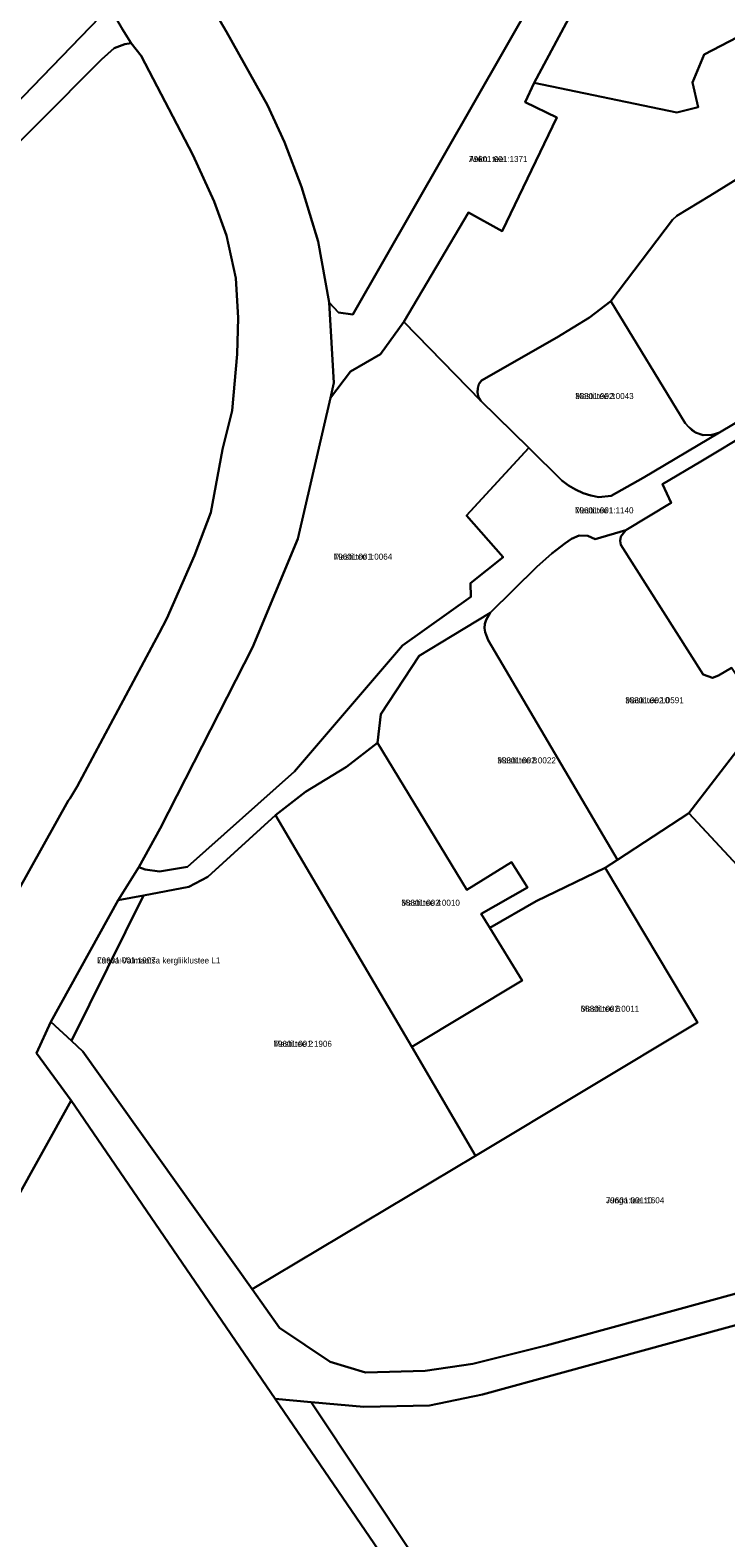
# Model space of a CAD drawing. Extents: x 625111 to 706696, y 6474150 to 6504223.
# Drawn here: x 638778 to 638950.5, y 6485129 to 6485502.8 of the extents above; entities that cross this region are included whole.
import ezdxf

# ---------------------------------------------------------------- set-up
doc = ezdxf.new("R2010")
doc.units = 0
for name, color, linetype in [('L_AADRESS', 7, 'Continuous'), ('PIIR', 7, 'Continuous'), ('TUNNUS', 7, 'Continuous')]:
    doc.layers.add(name, color=color, linetype=linetype)

msp = doc.modelspace()

# ---------------------------------------------------------------- linework, layer by layer
at = {"layer": 'PIIR'}
for points in [[(638782.67, 6485576.05), (638784.4, 6485579.3), (638790.71, 6485583.98), (638802.36, 6485586.41), (638817.08, 6485589.14), (638874.86, 6485597.99), (638894.65, 6485601.55), (638898.79, 6485597.02), (638907.54, 6485567.11), (638909.56, 6485556.39), (638909.87, 6485545.2), (638908.04, 6485527.28), (638906.6, 6485519.92), (638903.1, 6485511.25), (638858.04, 6485432.29), (638854.47, 6485432.84), (638852.13, 6485435.31), (638849.42, 6485450.41), (638845.25, 6485463.97), (638841.03, 6485475.01), (638836.81, 6485484.18), (638826.7, 6485502.4), (638802.18, 6485544.13)], [(638742.82, 6485568.79), (638781.99, 6485513.33), (638795.27, 6485512.53), (638796.61, 6485512.41), (638798.39, 6485509.3), (638797.64, 6485508.52), (638759.55, 6485469.21), (638758.48, 6485470.2), (638720.26, 6485531.5)], [(638616.72, 6485315.58), (638570.26, 6485268.85), (638564.72, 6485271.94), (638633.01, 6485342.2), (638632.31, 6485342.92), (638717.29, 6485427.39), (638718, 6485426.69), (638736.44, 6485445.14), (638750.53, 6485459.52), (638759.55, 6485469.21), (638797.64, 6485508.52), (638800.82, 6485503.13), (638803.01, 6485499.59), (638801.49, 6485499.35), (638798.84, 6485498.32), (638795.69, 6485495.51), (638747.94, 6485447.72), (638716.99, 6485416.28), (638708.55, 6485409.73)], [(638982.43, 6485427.28), (638978.84, 6485424.81), (638971.8, 6485420.65), (638963.59, 6485415.55), (638965.5, 6485412.9), (638948.95, 6485403.05), (638947.96, 6485402.69), (638946.97, 6485402.47), (638945.96, 6485402.38), (638944.88, 6485402.38), (638943.92, 6485402.7), (638942.97, 6485403.08), (638942.09, 6485403.64), (638941.29, 6485404.34), (638940.45, 6485405.39), (638921.96, 6485435.63), (638937.31, 6485455.82), (638938.31, 6485456.75), (638946.5, 6485461.77), (638953.47, 6485466.04), (638956.67, 6485467.85)], [(638948.95, 6485403.05), (638930.04, 6485391.8), (638922.06, 6485387.38), (638919.02, 6485387.06), (638916.99, 6485387.41), (638915.09, 6485388.01), (638913.21, 6485388.89), (638911.46, 6485389.89), (638909.87, 6485391.12), (638901.61, 6485399.25), (638889.74, 6485410.92), (638889.17, 6485411.85), (638888.93, 6485412.95), (638889, 6485414.06), (638889.27, 6485415.02), (638889.91, 6485415.96), (638908.61, 6485426.63), (638916.66, 6485431.54), (638921.96, 6485435.63), (638940.45, 6485405.39), (638941.29, 6485404.34), (638942.97, 6485403.08), (638944.88, 6485402.38), (638946.97, 6485402.47), (638947.96, 6485402.69)], [(638887.17, 6485365.73), (638887.26, 6485362.34), (638870.32, 6485350.21), (638843.57, 6485319.03), (638817.01, 6485295.37), (638810.1, 6485294.23), (638806.47, 6485294.72), (638804.94, 6485295.29), (638810.23, 6485304.88), (638833.13, 6485349.78), (638844.35, 6485376.71), (638852.48, 6485411.67), (638857.46, 6485418.19), (638864.83, 6485422.47), (638870.65, 6485430.46), (638889.74, 6485410.92), (638901.61, 6485399.25), (638886.18, 6485382.44), (638895.32, 6485372.15)], [(638925.68, 6485378.85), (638936.93, 6485385.6), (638934.77, 6485390.22), (638944.32, 6485395.86), (638956.91, 6485403.45), (638971.58, 6485412.28), (638989.73, 6485393.14), (638994.84, 6485389.32), (638990.6, 6485376.31), (638978.8, 6485363.93), (638966.42, 6485342.25), (638956.01, 6485341.65), (638955.05, 6485341.15), (638954.02, 6485341.48), (638951.88, 6485344.74), (638948.66, 6485342.79), (638947.17, 6485342.22), (638944.9, 6485343.05), (638924.49, 6485375.18), (638924.28, 6485376.2), (638924.43, 6485377.27)], [(638864.91, 6485333.2), (638874.47, 6485347.71), (638882.64, 6485352.68), (638892.04, 6485358.36), (638891.05, 6485356.61), (638890.75, 6485355.61), (638890.67, 6485354.58), (638890.85, 6485353.53), (638891.59, 6485351.53), (638923.6, 6485297.08), (638920.59, 6485295.11), (638903.44, 6485286.84), (638891.98, 6485280.22), (638889.85, 6485283.75), (638901.29, 6485290.24), (638897.36, 6485296.49), (638886.28, 6485289.68), (638864.1, 6485326.11)], [(638941.32, 6485308.7), (638960.45, 6485333.44), (638988.09, 6485314), (638994.99, 6485304.53), (638996.71, 6485300.14), (638970.95, 6485276.89)], [(638846.23, 6485314), (638856.41, 6485320.13), (638864.1, 6485326.11), (638886.28, 6485289.68), (638897.36, 6485296.49), (638901.29, 6485290.24), (638889.85, 6485283.75), (638891.98, 6485280.22), (638899.97, 6485267.18), (638872.63, 6485250.71), (638838.82, 6485308.17)], [(638788.23, 6485252.22), (638806.08, 6485288.26), (638817.33, 6485290.37), (638822.08, 6485292.86), (638838.82, 6485308.17), (638872.63, 6485250.71), (638888.4, 6485223.75), (638833.02, 6485190.63), (638791.06, 6485249.59)], [(638899.97, 6485267.18), (638891.98, 6485280.22), (638903.44, 6485286.84), (638920.59, 6485295.11), (638943.51, 6485256.8), (638888.4, 6485223.75), (638872.63, 6485250.71)], [(638788.23, 6485252.22), (638783.12, 6485256.93), (638799.77, 6485287.11), (638806.08, 6485288.26)], [(638931.59, 6485002.42), (638870.49, 6484835.17), (638723.26, 6485120.65), (638788.19, 6485237.4), (638838.72, 6485163.5), (638933.57, 6485024.77), (638938.01, 6485026.87), (639015.85, 6485066.04), (639017.1, 6485021.15)], [(638847.7, 6485162.63), (638860.71, 6485161.51), (638876.99, 6485161.83), (638890.17, 6485164.52), (639009.68, 6485197.31), (639015.85, 6485066.04), (638938.01, 6485026.87)], [(638838.72, 6485163.5), (638847.7, 6485162.63), (638938.01, 6485026.87), (638933.57, 6485024.77)]]:
    msp.add_lwpolyline(points, close=True, dxfattribs=at)
for points in [[(638802.18, 6485544.13), (638826.7, 6485502.4), (638836.81, 6485484.18), (638841.03, 6485475.01), (638845.25, 6485463.97), (638849.42, 6485450.41), (638852.13, 6485435.31), (638853.33, 6485415.33), (638852.48, 6485411.67), (638844.35, 6485376.71), (638833.13, 6485349.78), (638810.23, 6485304.88), (638804.94, 6485295.29), (638799.77, 6485287.11), (638783.12, 6485256.93), (638779.54, 6485249.16), (638788.19, 6485237.4), (638723.26, 6485120.65), (638562.67, 6484825.18), (638546.32, 6484825.91)], [(638912.12, 6485506.89), (638903, 6485489.78), (638900.75, 6485484.94), (638908.61, 6485481.14), (638895.06, 6485452.96), (638886.66, 6485457.57), (638870.65, 6485430.46), (638864.83, 6485422.47), (638857.46, 6485418.19), (638852.48, 6485411.67), (638853.33, 6485415.33), (638852.13, 6485435.31), (638854.47, 6485432.84), (638858.04, 6485432.29), (638903.1, 6485511.25)], [(639223.56, 6485267.38), (639212.2, 6485260.95), (639164.58, 6485309.39), (639145.62, 6485330.59), (639134.89, 6485344.87), (639122.99, 6485356.67), (639105.9, 6485372.5), (639098.87, 6485379.9), (639082.01, 6485394.58), (639069.1, 6485403.36), (639040.99, 6485429.13), (639026.45, 6485443.33), (639024.74, 6485447.28), (639021.42, 6485450.35), (638977.35, 6485491.09), (638966.87, 6485497.91), (638953.41, 6485501.05), (638945.14, 6485496.81), (638942.22, 6485489.86), (638943.68, 6485483.71), (638938.35, 6485482.36), (638903, 6485489.78), (638912.12, 6485506.89)], [(638528.72, 6484862.32), (638686.3, 6485153.17), (638689.4, 6485161.09), (638736.24, 6485245.3), (638745.8, 6485237.26), (638787.4, 6485311.71), (638787.91, 6485312.41), (638789.67, 6485315.31), (638809.97, 6485353.32), (638811.86, 6485356.95), (638818.71, 6485372.53), (638822.76, 6485383.22), (638825.69, 6485398.82), (638828.12, 6485408.53), (638829.36, 6485422.49), (638829.6, 6485431.48), (638829.02, 6485441.3), (638826.69, 6485451.91), (638823.64, 6485460.32), (638818.36, 6485471.86), (638805.53, 6485496.41), (638803.01, 6485499.59), (638800.82, 6485503.13)], [(638747.94, 6485447.72), (638795.69, 6485495.51), (638798.84, 6485498.32), (638801.49, 6485499.35), (638803.01, 6485499.59), (638805.53, 6485496.41), (638818.36, 6485471.86), (638823.64, 6485460.32), (638826.69, 6485451.91), (638829.02, 6485441.3), (638829.6, 6485431.48), (638829.36, 6485422.49), (638828.12, 6485408.53), (638825.69, 6485398.82), (638822.76, 6485383.22), (638818.71, 6485372.53), (638811.86, 6485356.95), (638809.97, 6485353.32), (638789.67, 6485315.31), (638787.91, 6485312.41), (638787.4, 6485311.71), (638745.8, 6485237.26)], [(638953.47, 6485466.04), (638946.5, 6485461.77), (638938.31, 6485456.75), (638937.31, 6485455.82), (638921.96, 6485435.63), (638916.66, 6485431.54), (638908.61, 6485426.63), (638889.91, 6485415.96), (638889.27, 6485415.02), (638889, 6485414.06), (638888.93, 6485412.95), (638889.17, 6485411.85), (638889.74, 6485410.92), (638870.65, 6485430.46), (638886.66, 6485457.57), (638895.06, 6485452.96), (638908.61, 6485481.14), (638900.75, 6485484.94), (638903, 6485489.78), (638938.35, 6485482.36), (638943.68, 6485483.71), (638942.22, 6485489.86), (638945.14, 6485496.81), (638953.41, 6485501.05)], [(638956.91, 6485403.45), (638944.32, 6485395.86), (638934.77, 6485390.22), (638936.93, 6485385.6), (638925.68, 6485378.85), (638918.07, 6485376.58), (638916.25, 6485377.47), (638914.16, 6485377.51), (638912.2, 6485376.68), (638910.54, 6485375.55), (638907.37, 6485373.04), (638903.62, 6485369.72), (638892.04, 6485358.36), (638882.64, 6485352.68), (638874.47, 6485347.71), (638864.91, 6485333.2), (638864.1, 6485326.11), (638856.41, 6485320.13), (638846.23, 6485314), (638838.82, 6485308.17), (638822.08, 6485292.86), (638817.33, 6485290.37), (638806.08, 6485288.26), (638799.77, 6485287.11), (638804.94, 6485295.29), (638806.47, 6485294.72), (638810.1, 6485294.23), (638817.01, 6485295.37), (638843.57, 6485319.03), (638870.32, 6485350.21), (638887.26, 6485362.34), (638887.17, 6485365.73), (638895.32, 6485372.15), (638886.18, 6485382.44), (638901.61, 6485399.25), (638909.87, 6485391.12), (638911.46, 6485389.89), (638913.21, 6485388.89), (638915.09, 6485388.01), (638916.99, 6485387.41), (638919.02, 6485387.06), (638922.06, 6485387.38), (638930.04, 6485391.8), (638948.95, 6485403.05), (638965.5, 6485412.9)], [(638960.45, 6485333.44), (638941.32, 6485308.7), (638923.6, 6485297.08), (638891.59, 6485351.53), (638890.85, 6485353.53), (638890.67, 6485354.58), (638890.75, 6485355.61), (638891.05, 6485356.61), (638892.04, 6485358.36), (638903.62, 6485369.72), (638907.37, 6485373.04), (638910.54, 6485375.55), (638912.2, 6485376.68), (638914.16, 6485377.51), (638916.25, 6485377.47), (638918.07, 6485376.58), (638925.68, 6485378.85), (638924.43, 6485377.27), (638924.28, 6485376.2), (638924.49, 6485375.18), (638944.9, 6485343.05), (638947.17, 6485342.22), (638948.66, 6485342.79), (638951.88, 6485344.74)], [(639008.05, 6485204.62), (638905.91, 6485176.68), (638887.78, 6485172.14), (638875.98, 6485170.45), (638861.18, 6485169.96), (638852.35, 6485172.64), (638839.8, 6485181.07), (638833.02, 6485190.63), (638888.4, 6485223.75), (638943.51, 6485256.8), (638920.59, 6485295.11), (638923.6, 6485297.08), (638941.32, 6485308.7), (638970.95, 6485276.89)], [(639009.68, 6485197.31), (638890.17, 6485164.52), (638876.99, 6485161.83), (638860.71, 6485161.51), (638847.7, 6485162.63), (638838.72, 6485163.5), (638788.19, 6485237.4), (638779.54, 6485249.16), (638783.12, 6485256.93), (638788.23, 6485252.22), (638791.06, 6485249.59), (638833.02, 6485190.63), (638839.8, 6485181.07), (638852.35, 6485172.64), (638861.18, 6485169.96), (638875.98, 6485170.45), (638887.78, 6485172.14), (638905.91, 6485176.68), (639008.05, 6485204.62)]]:
    msp.add_lwpolyline(points, dxfattribs=at)

# ---------------------------------------------------------------- texts
at = {"layer": 'L_AADRESS'}
for s, p in [('Ankru tee', (638886.82, 6485470.1)), ('Masti tee 3', (638913.14, 6485411.34)), ('Masti tee', (638913.11, 6485383.01)), ('Masti tee 1', (638853.27, 6485371.53)), ('Masti tee 10', (638925.56, 6485335.93)), ('Masti tee 8', (638893.85, 6485321.01)), ('Masti tee 4', (638870.05, 6485285.71)), ('Laeva-Valmaotsa kergliiklustee L1', (638794.6, 6485271.41)), ('Masti tee 6', (638914.52, 6485259.43)), ('Masti tee 2', (638838.31, 6485250.75)), ('Junga tee 10', (638920.74, 6485211.94))]:
    msp.add_text(s, height=1.5, dxfattribs=at).set_placement(p)
at = {"layer": 'TUNNUS'}
for s, p in [('79601:001:1371', (638886.82, 6485470.1)), ('38301:002:0043', (638913.14, 6485411.34)), ('79601:001:1140', (638913.11, 6485383.01)), ('79601:001:0064', (638853.27, 6485371.53)), ('38301:002:0591', (638925.56, 6485335.93)), ('38301:002:0022', (638893.85, 6485321.01)), ('38301:002:0010', (638870.05, 6485285.71)), ('79601:001:1907', (638794.6, 6485271.41)), ('38301:002:0011', (638914.52, 6485259.43)), ('79601:001:1906', (638838.31, 6485250.75)), ('79601:001:1604', (638920.74, 6485211.94))]:
    msp.add_text(s, height=1.5, dxfattribs=at).set_placement(p)

doc.saveas('drawing.dxf')
